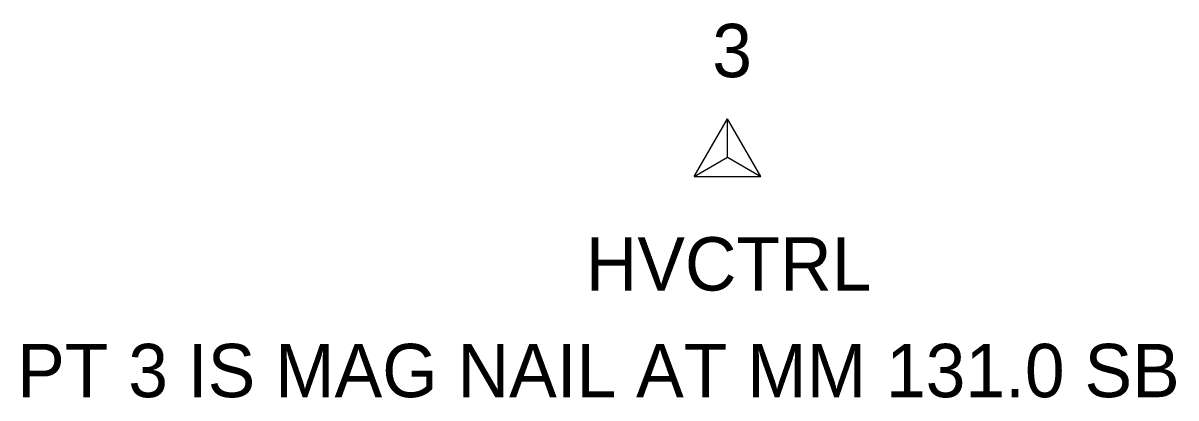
# Model space of a CAD drawing. Extents: x 1761340 to 1763889, y 696770 to 706023.
# Drawn here: x 1762081.23 to 1762124.42, y 705021.18 to 705035.24 of the extents above; entities that cross this region are included whole.
import ezdxf

# ---------------------------------------------------------------- set-up
doc = ezdxf.new("R2010")
doc.units = 0
for name, color, linetype in [('C_A', 7, 'Continuous'), ('C_C', 7, 'Continuous'), ('C_I', 7, 'Continuous'), ('CPSM', 7, 'Continuous')]:
    doc.layers.add(name, color=color, linetype=linetype)

msp = doc.modelspace()

# ---------------------------------------------------------------- linework, layer by layer
at = {"layer": 'CPSM'}
for p, q in [((1762106.364, 705029.487), (1762107.614, 705031.652)), ((1762106.364, 705029.487), (1762107.614, 705031.652)), ((1762106.364, 705029.487), (1762107.614, 705031.652)), ((1762106.364, 705029.487), (1762107.614, 705031.652)), ((1762108.864, 705029.487), (1762107.614, 705031.652)), ((1762107.614, 705030.208), (1762107.614, 705031.652)), ((1762108.864, 705029.487), (1762107.614, 705031.652)), ((1762107.614, 705030.208), (1762107.614, 705031.652)), ((1762108.864, 705029.487), (1762107.614, 705031.652)), ((1762107.614, 705030.208), (1762107.614, 705031.652)), ((1762108.864, 705029.487), (1762107.614, 705031.652)), ((1762107.614, 705030.208), (1762107.614, 705031.652)), ((1762106.364, 705029.487), (1762107.614, 705030.208)), ((1762106.364, 705029.487), (1762107.614, 705030.208)), ((1762106.364, 705029.487), (1762107.614, 705030.208)), ((1762106.364, 705029.487), (1762107.614, 705030.208)), ((1762107.614, 705030.208), (1762107.614, 705030.208)), ((1762107.614, 705030.208), (1762108.864, 705029.487)), ((1762107.614, 705030.208), (1762107.614, 705030.208)), ((1762107.614, 705030.208), (1762108.864, 705029.487)), ((1762107.614, 705030.208), (1762107.614, 705030.208)), ((1762107.614, 705030.208), (1762108.864, 705029.487)), ((1762107.614, 705030.208), (1762107.614, 705030.208)), ((1762107.614, 705030.208), (1762108.864, 705029.487)), ((1762106.364, 705029.487), (1762108.864, 705029.487)), ((1762106.364, 705029.487), (1762108.864, 705029.487)), ((1762106.364, 705029.487), (1762108.864, 705029.487)), ((1762106.364, 705029.487), (1762108.864, 705029.487))]:
    msp.add_line(p, q, dxfattribs=at)

# ---------------------------------------------------------------- texts
at = {"layer": 'C_A'}
msp.add_text('HVCTRL', height=2, dxfattribs=at).set_placement((1762102.307, 705025.208))
msp.add_text('HVCTRL', height=2, dxfattribs=at).set_placement((1762102.307, 705025.208))
msp.add_text('HVCTRL', height=2, dxfattribs=at).set_placement((1762102.307, 705025.208))
msp.add_text('HVCTRL', height=2, dxfattribs=at).set_placement((1762102.307, 705025.208))
at = {"layer": 'C_C'}
msp.add_text('PT 3 IS MAG NAIL AT MM 131.0 SB', height=2, dxfattribs=at).set_placement((1762081.009, 705021.208))
msp.add_text('PT 3 IS MAG NAIL AT MM 131.0 SB', height=2, dxfattribs=at).set_placement((1762081.009, 705021.208))
msp.add_text('PT 3 IS MAG NAIL AT MM 131.0 SB', height=2, dxfattribs=at).set_placement((1762081.009, 705021.208))
msp.add_text('PT 3 IS MAG NAIL AT MM 131.0 SB', height=2, dxfattribs=at).set_placement((1762081.009, 705021.208))
at = {"layer": 'C_I'}
msp.add_text('3', height=2, dxfattribs=at).set_placement((1762107.047, 705033.208))
msp.add_text('3', height=2, dxfattribs=at).set_placement((1762107.047, 705033.208))
msp.add_text('3', height=2, dxfattribs=at).set_placement((1762107.047, 705033.208))
msp.add_text('3', height=2, dxfattribs=at).set_placement((1762107.047, 705033.208))

doc.saveas('drawing.dxf')
